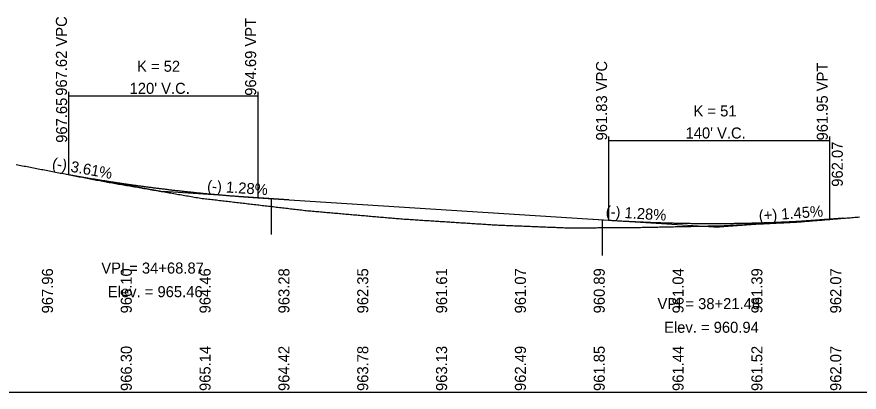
# Model space of a CAD drawing. Extents: x 1619269 to 1623088, y 1189107 to 1192385.
# Drawn here: x 1622052 to 1622587, y 1190357 to 1190595 of the extents above; entities that cross this region are included whole.
import ezdxf

# ---------------------------------------------------------------- set-up
doc = ezdxf.new("R2010")
doc.units = 0
for name, color, linetype in [('RD_DDB_GradeTX', 7, 'Continuous'), ('RD_DDB_Profile_EX', 7, 'Continuous'), ('RD_DDB_Profile_Lbl', 7, 'Continuous'), ('RD_DDB_Profile_PR', 7, 'Continuous'), ('RD_DDB_StripGrade', 7, 'Continuous'), ('RD_DDB_VCLbl', 7, 'Continuous'), ('RD_GPK_Profile_Cell', 7, 'Continuous'), ('RD_Sketch1', 7, 'Continuous')]:
    doc.layers.add(name, color=color, linetype=linetype)

msp = doc.modelspace()

# ---------------------------------------------------------------- linework, layer by layer
at = {"layer": 'RD_DDB_GradeTX'}
for p, q in [((1622084.17, 1190494.88), (1622145.04, 1190483.9)), ((1622224.88, 1190478.79), (1622145.04, 1190483.9)), ((1622417.82, 1190466.42), (1622497.65, 1190461.3)), ((1622576.17, 1190466.98), (1622497.65, 1190461.3))]:
    msp.add_line(p, q, dxfattribs=at)
at = {"layer": 'RD_DDB_Profile_EX'}
for points in [[(1622051.84, 1190501.04), (1622052.84, 1190500.86), (1622053.84, 1190500.68), (1622054.84, 1190500.5), (1622055.84, 1190500.33), (1622056.84, 1190500.15), (1622057.84, 1190499.97), (1622058.84, 1190499.78), (1622059.84, 1190499.58), (1622060.84, 1190499.39), (1622061.84, 1190499.2), (1622062.84, 1190499), (1622063.84, 1190498.81), (1622064.84, 1190498.62), (1622065.84, 1190498.42), (1622066.84, 1190498.23), (1622067.84, 1190498.04), (1622068.84, 1190497.84), (1622069.84, 1190497.65), (1622070.84, 1190497.46), (1622071.84, 1190497.26), (1622072.84, 1190497.07), (1622073.84, 1190496.88), (1622074.84, 1190496.68), (1622075.84, 1190496.49), (1622076.84, 1190496.3), (1622077.84, 1190496.1), (1622078.84, 1190495.91), (1622079.84, 1190495.71), (1622080.84, 1190495.52), (1622081.84, 1190495.33), (1622082.84, 1190495.13), (1622083.84, 1190494.94), (1622084.84, 1190494.75), (1622085.84, 1190494.55), (1622086.84, 1190494.36), (1622087.84, 1190494.17), (1622088.84, 1190493.97), (1622089.84, 1190493.78), (1622090.84, 1190493.59), (1622091.84, 1190493.39), (1622092.84, 1190493.2), (1622093.84, 1190493.01), (1622094.84, 1190492.81), (1622095.84, 1190492.62), (1622096.84, 1190492.43), (1622097.84, 1190492.23), (1622098.84, 1190492.04), (1622099.84, 1190491.85), (1622100.84, 1190491.65), (1622101.84, 1190491.46), (1622102.84, 1190491.27), (1622103.84, 1190491.07), (1622104.84, 1190490.88), (1622105.84, 1190490.68), (1622106.84, 1190490.49), (1622107.84, 1190490.3), (1622108.84, 1190490.11), (1622109.84, 1190489.95), (1622110.84, 1190489.77), (1622111.84, 1190489.6), (1622112.84, 1190489.43), (1622113.84, 1190489.26), (1622114.84, 1190489.08), (1622115.84, 1190488.91), (1622116.84, 1190488.74), (1622117.84, 1190488.56), (1622118.84, 1190488.39), (1622119.84, 1190488.22), (1622120.84, 1190488.05), (1622121.84, 1190487.87), (1622122.84, 1190487.7), (1622123.84, 1190487.53), (1622124.84, 1190487.35)], [(1622124.84, 1190487.35), (1622125.84, 1190487.18), (1622126.84, 1190487.01), (1622127.84, 1190486.84), (1622128.84, 1190486.66), (1622129.84, 1190486.49), (1622130.84, 1190486.32), (1622131.84, 1190486.14), (1622132.84, 1190485.97), (1622133.84, 1190485.8), (1622134.84, 1190485.63), (1622135.84, 1190485.45), (1622136.84, 1190485.28), (1622137.84, 1190485.11), (1622138.84, 1190484.93), (1622139.84, 1190484.76), (1622140.84, 1190484.59), (1622141.84, 1190484.42), (1622142.84, 1190484.24), (1622143.84, 1190484.07), (1622144.84, 1190483.9), (1622145.84, 1190483.72), (1622146.84, 1190483.55), (1622147.84, 1190483.38), (1622148.84, 1190483.21), (1622149.84, 1190483.03), (1622150.84, 1190482.86), (1622151.84, 1190482.69), (1622152.84, 1190482.51), (1622153.84, 1190482.34), (1622154.84, 1190482.17), (1622155.84, 1190482), (1622156.84, 1190481.82), (1622157.84, 1190481.65), (1622158.84, 1190481.48), (1622159.84, 1190481.3), (1622160.84, 1190481.13), (1622161.84, 1190480.96), (1622162.84, 1190480.79), (1622163.84, 1190480.61), (1622164.84, 1190480.44), (1622165.84, 1190480.27), (1622166.84, 1190480.09), (1622167.84, 1190479.92), (1622168.84, 1190479.77), (1622169.84, 1190479.64), (1622170.84, 1190479.53), (1622171.84, 1190479.41), (1622172.84, 1190479.29), (1622173.84, 1190479.18), (1622174.84, 1190479.06), (1622175.84, 1190478.94), (1622176.84, 1190478.82), (1622177.84, 1190478.71), (1622178.84, 1190478.59), (1622179.84, 1190478.47), (1622180.84, 1190478.36), (1622181.84, 1190478.24), (1622182.84, 1190478.12), (1622183.84, 1190478), (1622184.84, 1190477.89), (1622185.84, 1190477.77), (1622186.84, 1190477.65), (1622187.84, 1190477.53), (1622188.84, 1190477.42), (1622189.84, 1190477.3), (1622190.84, 1190477.18), (1622191.84, 1190477.07), (1622192.84, 1190476.95), (1622193.84, 1190476.83), (1622194.84, 1190476.71), (1622195.84, 1190476.6), (1622196.84, 1190476.48), (1622197.84, 1190476.36), (1622198.84, 1190476.24), (1622199.84, 1190476.13), (1622200.84, 1190476.01), (1622201.84, 1190475.89), (1622202.84, 1190475.78), (1622203.84, 1190475.66), (1622204.84, 1190475.54), (1622205.84, 1190475.42), (1622206.84, 1190475.31), (1622207.84, 1190475.19), (1622208.84, 1190475.07), (1622209.84, 1190474.96), (1622210.84, 1190474.84), (1622211.84, 1190474.72), (1622212.84, 1190474.6), (1622213.84, 1190474.49), (1622214.84, 1190474.37), (1622215.84, 1190474.25), (1622216.84, 1190474.13), (1622217.84, 1190474.02), (1622218.84, 1190473.9), (1622219.84, 1190473.78), (1622220.84, 1190473.67), (1622221.84, 1190473.55), (1622222.84, 1190473.43), (1622223.84, 1190473.31), (1622224.84, 1190473.2)], [(1622224.84, 1190473.2), (1622225.84, 1190473.08), (1622226.84, 1190472.96), (1622227.84, 1190472.84), (1622228.84, 1190472.73), (1622229.84, 1190472.61), (1622230.84, 1190472.49), (1622231.84, 1190472.38), (1622232.84, 1190472.26), (1622233.84, 1190472.14), (1622234.84, 1190472.02), (1622235.84, 1190471.91), (1622236.84, 1190471.8), (1622237.84, 1190471.71), (1622238.84, 1190471.62), (1622239.84, 1190471.54), (1622240.84, 1190471.45), (1622241.84, 1190471.36), (1622242.84, 1190471.27), (1622243.84, 1190471.19), (1622244.84, 1190471.1), (1622245.84, 1190471.01), (1622246.84, 1190470.93), (1622247.84, 1190470.84), (1622248.84, 1190470.75), (1622249.84, 1190470.66), (1622250.84, 1190470.58), (1622251.84, 1190470.49), (1622252.84, 1190470.4), (1622253.84, 1190470.31), (1622254.84, 1190470.23), (1622255.84, 1190470.14), (1622256.84, 1190470.05), (1622257.84, 1190469.97), (1622258.84, 1190469.88), (1622259.84, 1190469.79), (1622260.84, 1190469.7), (1622261.84, 1190469.62), (1622262.84, 1190469.53), (1622263.84, 1190469.44), (1622264.84, 1190469.36), (1622265.84, 1190469.27), (1622266.84, 1190469.18), (1622267.84, 1190469.09), (1622268.84, 1190469.01), (1622269.84, 1190468.92), (1622270.84, 1190468.83), (1622271.84, 1190468.75), (1622272.84, 1190468.66), (1622273.84, 1190468.57), (1622274.84, 1190468.48), (1622275.84, 1190468.4), (1622276.84, 1190468.31), (1622277.84, 1190468.22), (1622278.84, 1190468.13), (1622279.84, 1190468.05), (1622280.84, 1190467.96), (1622281.84, 1190467.87), (1622282.84, 1190467.79), (1622283.84, 1190467.7), (1622284.84, 1190467.61), (1622285.84, 1190467.52), (1622286.84, 1190467.44), (1622287.84, 1190467.35), (1622288.84, 1190467.26), (1622289.84, 1190467.18), (1622290.84, 1190467.09), (1622291.84, 1190467), (1622292.84, 1190466.91), (1622293.84, 1190466.83), (1622294.84, 1190466.74), (1622295.84, 1190466.65), (1622296.84, 1190466.57), (1622297.84, 1190466.51), (1622298.84, 1190466.44), (1622299.84, 1190466.38), (1622300.84, 1190466.32), (1622301.84, 1190466.25), (1622302.84, 1190466.19), (1622303.84, 1190466.12), (1622304.84, 1190466.06), (1622305.84, 1190466), (1622306.84, 1190465.93), (1622307.84, 1190465.87), (1622308.84, 1190465.8), (1622309.84, 1190465.74), (1622310.84, 1190465.68), (1622311.84, 1190465.61), (1622312.84, 1190465.55), (1622313.84, 1190465.48), (1622314.84, 1190465.42), (1622315.84, 1190465.35), (1622316.84, 1190465.29), (1622317.84, 1190465.23), (1622318.84, 1190465.16), (1622319.84, 1190465.1), (1622320.84, 1190465.03), (1622321.84, 1190464.97), (1622322.84, 1190464.91), (1622323.84, 1190464.84), (1622324.84, 1190464.78)], [(1622324.84, 1190464.78), (1622325.84, 1190464.71), (1622326.84, 1190464.65), (1622327.84, 1190464.59), (1622328.84, 1190464.52), (1622329.84, 1190464.46), (1622330.84, 1190464.39), (1622331.84, 1190464.33), (1622332.84, 1190464.27), (1622333.84, 1190464.2), (1622334.84, 1190464.14), (1622335.84, 1190464.07), (1622336.84, 1190464.01), (1622337.84, 1190463.95), (1622338.84, 1190463.88), (1622339.84, 1190463.82), (1622340.84, 1190463.75), (1622341.84, 1190463.69), (1622342.84, 1190463.62), (1622343.84, 1190463.56), (1622344.84, 1190463.5), (1622345.84, 1190463.43), (1622346.84, 1190463.37), (1622347.84, 1190463.3), (1622348.84, 1190463.24), (1622349.84, 1190463.18), (1622350.84, 1190463.11), (1622351.84, 1190463.05), (1622352.84, 1190462.98), (1622353.84, 1190462.92), (1622354.84, 1190462.86), (1622355.84, 1190462.79), (1622356.84, 1190462.74), (1622357.84, 1190462.69), (1622358.84, 1190462.65), (1622359.84, 1190462.61), (1622360.84, 1190462.57), (1622361.84, 1190462.53), (1622362.84, 1190462.49), (1622363.84, 1190462.45), (1622364.84, 1190462.41), (1622365.84, 1190462.37), (1622366.84, 1190462.33), (1622367.84, 1190462.29), (1622368.84, 1190462.25), (1622369.84, 1190462.21), (1622370.84, 1190462.17), (1622371.84, 1190462.13), (1622372.84, 1190462.09), (1622373.84, 1190462.05), (1622374.84, 1190462.01), (1622375.84, 1190461.97), (1622376.84, 1190461.93), (1622377.84, 1190461.89), (1622378.84, 1190461.85), (1622379.84, 1190461.81), (1622380.84, 1190461.77), (1622381.84, 1190461.73), (1622382.84, 1190461.69), (1622383.84, 1190461.65), (1622384.84, 1190461.61), (1622385.84, 1190461.57), (1622386.84, 1190461.52), (1622387.84, 1190461.48), (1622388.84, 1190461.44), (1622389.84, 1190461.4), (1622390.84, 1190461.36), (1622391.84, 1190461.32), (1622392.84, 1190461.28), (1622393.84, 1190461.24), (1622394.84, 1190461.2), (1622395.84, 1190461.16), (1622396.84, 1190461.11), (1622397.84, 1190461.07), (1622398.84, 1190461.03), (1622399.84, 1190460.99), (1622400.84, 1190460.95), (1622401.84, 1190460.93), (1622402.84, 1190460.94), (1622403.84, 1190460.94), (1622404.84, 1190460.95), (1622405.84, 1190460.95), (1622406.84, 1190460.96), (1622407.84, 1190460.96), (1622408.84, 1190460.97), (1622409.84, 1190460.97), (1622410.84, 1190460.98), (1622411.84, 1190460.98), (1622412.84, 1190460.99), (1622413.84, 1190460.99), (1622414.84, 1190461), (1622415.84, 1190461), (1622416.84, 1190461.01), (1622417.84, 1190461.01), (1622418.84, 1190461.02), (1622419.84, 1190461.02), (1622420.84, 1190461.03), (1622421.84, 1190461.03), (1622422.84, 1190461.04), (1622423.84, 1190461.04), (1622424.84, 1190461.05)], [(1622524.84, 1190463.5), (1622525.84, 1190463.55), (1622526.84, 1190463.6), (1622527.84, 1190463.65), (1622528.84, 1190463.7), (1622529.84, 1190463.75), (1622530.84, 1190463.8), (1622531.84, 1190463.85), (1622532.84, 1190463.9), (1622533.84, 1190463.95), (1622534.84, 1190464), (1622535.84, 1190464.05), (1622536.84, 1190464.1), (1622537.84, 1190464.14), (1622538.84, 1190464.19), (1622539.84, 1190464.24), (1622540.84, 1190464.29), (1622541.84, 1190464.34), (1622542.84, 1190464.39), (1622543.84, 1190464.44), (1622544.84, 1190464.49), (1622545.84, 1190464.53), (1622546.84, 1190464.58), (1622547.84, 1190464.65), (1622548.84, 1190464.74), (1622549.84, 1190464.82), (1622550.84, 1190464.9), (1622551.84, 1190464.98), (1622552.84, 1190465.06), (1622553.84, 1190465.15), (1622554.84, 1190465.23), (1622555.84, 1190465.31), (1622556.84, 1190465.39), (1622557.84, 1190465.48), (1622558.84, 1190465.56), (1622559.84, 1190465.64), (1622560.84, 1190465.72), (1622561.84, 1190465.81), (1622562.84, 1190465.89), (1622563.84, 1190465.97), (1622564.84, 1190466.05), (1622565.84, 1190466.13), (1622566.84, 1190466.22), (1622567.84, 1190466.3), (1622568.84, 1190466.38), (1622569.84, 1190466.46), (1622570.84, 1190466.55), (1622571.84, 1190466.63), (1622572.84, 1190466.71), (1622573.84, 1190466.79), (1622574.84, 1190466.87), (1622575.84, 1190466.96), (1622576.84, 1190467.04), (1622577.84, 1190467.12), (1622578.84, 1190467.2), (1622579.84, 1190467.29), (1622580.84, 1190467.37), (1622581.84, 1190467.45), (1622582.84, 1190467.53), (1622583.84, 1190467.62), (1622584.84, 1190467.7), (1622585.84, 1190467.78), (1622586.84, 1190467.86)], [(1622424.84, 1190461.05), (1622425.84, 1190461.05), (1622426.84, 1190461.06), (1622427.84, 1190461.06), (1622428.84, 1190461.07), (1622429.84, 1190461.07), (1622430.84, 1190461.08), (1622431.84, 1190461.08), (1622432.84, 1190461.09), (1622433.84, 1190461.09), (1622434.84, 1190461.1), (1622435.84, 1190461.1), (1622436.84, 1190461.11), (1622437.84, 1190461.11), (1622438.84, 1190461.12), (1622439.84, 1190461.12), (1622440.84, 1190461.13), (1622441.84, 1190461.13), (1622442.84, 1190461.14), (1622443.84, 1190461.15), (1622444.84, 1190461.17), (1622445.84, 1190461.19), (1622446.84, 1190461.21), (1622447.84, 1190461.23), (1622448.84, 1190461.25), (1622449.84, 1190461.27), (1622450.84, 1190461.29), (1622451.84, 1190461.31), (1622452.84, 1190461.33), (1622453.84, 1190461.35), (1622454.84, 1190461.37), (1622455.84, 1190461.39), (1622456.84, 1190461.41), (1622457.84, 1190461.43), (1622458.84, 1190461.45), (1622459.84, 1190461.47), (1622460.84, 1190461.49), (1622461.84, 1190461.51), (1622462.84, 1190461.53), (1622463.84, 1190461.55), (1622464.84, 1190461.57), (1622465.84, 1190461.59), (1622466.84, 1190461.61), (1622467.84, 1190461.63), (1622468.84, 1190461.65), (1622469.84, 1190461.67), (1622470.84, 1190461.69), (1622471.84, 1190461.71), (1622472.84, 1190461.73), (1622473.84, 1190461.75), (1622474.84, 1190461.77), (1622475.84, 1190461.79), (1622476.84, 1190461.81), (1622477.84, 1190461.83), (1622478.84, 1190461.85), (1622479.84, 1190461.87), (1622480.84, 1190461.89), (1622481.84, 1190461.91), (1622482.84, 1190461.93), (1622483.84, 1190461.95), (1622484.84, 1190461.97), (1622485.84, 1190461.99), (1622486.84, 1190462.01), (1622487.84, 1190462.03), (1622488.84, 1190462.05), (1622489.84, 1190462.07), (1622490.84, 1190462.09), (1622491.84, 1190462.11), (1622492.84, 1190462.13), (1622493.84, 1190462.15), (1622494.84, 1190462.17), (1622495.84, 1190462.19), (1622496.84, 1190462.21), (1622497.84, 1190462.23), (1622498.84, 1190462.25), (1622499.84, 1190462.29), (1622500.84, 1190462.32), (1622501.84, 1190462.37), (1622502.84, 1190462.42), (1622503.84, 1190462.47), (1622504.84, 1190462.52), (1622505.84, 1190462.57), (1622506.84, 1190462.62), (1622507.84, 1190462.67), (1622508.84, 1190462.72), (1622509.84, 1190462.77), (1622510.84, 1190462.82), (1622511.84, 1190462.86), (1622512.84, 1190462.91), (1622513.84, 1190462.96), (1622514.84, 1190463.01), (1622515.84, 1190463.06), (1622516.84, 1190463.11), (1622517.84, 1190463.16), (1622518.84, 1190463.21), (1622519.84, 1190463.26), (1622520.84, 1190463.31), (1622521.84, 1190463.36), (1622522.84, 1190463.41), (1622523.84, 1190463.46), (1622524.84, 1190463.5)]]:
    msp.add_lwpolyline(points, dxfattribs=at)
at = {"layer": 'RD_DDB_Profile_PR'}
for p, q in [((1622084.17, 1190494.88), (1622085.04, 1190494.72)), ((1622205.04, 1190480.06), (1622427.65, 1190465.79)), ((1622567.65, 1190466.37), (1622576.17, 1190466.98))]:
    msp.add_line(p, q, dxfattribs=at)
for points in [[(1622085.04, 1190494.72), (1622087.44, 1190494.29), (1622089.84, 1190493.87), (1622092.24, 1190493.45), (1622094.64, 1190493.03), (1622097.04, 1190492.63), (1622099.44, 1190492.22), (1622101.84, 1190491.83), (1622104.24, 1190491.44), (1622106.64, 1190491.05), (1622109.04, 1190490.67), (1622111.44, 1190490.3), (1622113.84, 1190489.93), (1622116.24, 1190489.57), (1622118.64, 1190489.21), (1622121.04, 1190488.86), (1622123.44, 1190488.51), (1622125.84, 1190488.17), (1622128.24, 1190487.84), (1622130.64, 1190487.51), (1622133.04, 1190487.18), (1622135.44, 1190486.86), (1622137.84, 1190486.55), (1622140.24, 1190486.24), (1622142.64, 1190485.94), (1622145.04, 1190485.65), (1622147.44, 1190485.36), (1622149.84, 1190485.07), (1622152.24, 1190484.79), (1622154.64, 1190484.52), (1622157.04, 1190484.25), (1622159.44, 1190483.99), (1622161.84, 1190483.73), (1622164.24, 1190483.48), (1622166.64, 1190483.23), (1622169.04, 1190482.99), (1622171.44, 1190482.76), (1622173.84, 1190482.53), (1622176.24, 1190482.31), (1622178.64, 1190482.09), (1622181.04, 1190481.88), (1622183.44, 1190481.67), (1622185.84, 1190481.47), (1622188.24, 1190481.27), (1622190.64, 1190481.08), (1622193.04, 1190480.9), (1622195.44, 1190480.72), (1622197.84, 1190480.55), (1622200.24, 1190480.38), (1622202.64, 1190480.22), (1622205.04, 1190480.06)], [(1622427.65, 1190465.79), (1622430.45, 1190465.61), (1622433.25, 1190465.45), (1622436.05, 1190465.29), (1622438.85, 1190465.13), (1622441.65, 1190464.99), (1622444.45, 1190464.85), (1622447.25, 1190464.72), (1622450.05, 1190464.6), (1622452.85, 1190464.48), (1622455.65, 1190464.38), (1622458.45, 1190464.28), (1622461.25, 1190464.19), (1622464.05, 1190464.1), (1622466.85, 1190464.03), (1622469.65, 1190463.96), (1622472.45, 1190463.9), (1622475.25, 1190463.84), (1622478.05, 1190463.8), (1622480.85, 1190463.76), (1622483.65, 1190463.73), (1622486.45, 1190463.71), (1622489.25, 1190463.69), (1622492.05, 1190463.68), (1622494.85, 1190463.68), (1622497.65, 1190463.69), (1622500.45, 1190463.71), (1622503.25, 1190463.73), (1622506.05, 1190463.76), (1622508.85, 1190463.8), (1622511.65, 1190463.84), (1622514.45, 1190463.9), (1622517.25, 1190463.96), (1622520.05, 1190464.03), (1622522.85, 1190464.1), (1622525.65, 1190464.19), (1622528.45, 1190464.28), (1622531.25, 1190464.38), (1622534.05, 1190464.49), (1622536.85, 1190464.6), (1622539.65, 1190464.72), (1622542.45, 1190464.85), (1622545.25, 1190464.99), (1622548.05, 1190465.14), (1622550.85, 1190465.29), (1622553.65, 1190465.45), (1622556.45, 1190465.62), (1622559.25, 1190465.79), (1622562.05, 1190465.98), (1622564.85, 1190466.17), (1622567.65, 1190466.37)]]:
    msp.add_spline(points, degree=3, dxfattribs=at)
at = {"layer": 'RD_DDB_VCLbl'}
for p, q in [((1622085.04, 1190547.22), (1622085.04, 1190494.72)), ((1622085.04, 1190544.72), (1622205.04, 1190544.72)), ((1622205.04, 1190547.22), (1622205.04, 1190480.06)), ((1622427.65, 1190518.87), (1622427.65, 1190465.79)), ((1622567.65, 1190518.87), (1622567.65, 1190466.37)), ((1622427.65, 1190516.37), (1622567.65, 1190516.37))]:
    msp.add_line(p, q, dxfattribs=at)
at = {"layer": 'RD_GPK_Profile_Cell'}
msp.add_line((1621576.17, 1190356.62), (1623076.17, 1190356.62), dxfattribs=at)
at = {"layer": 'RD_Sketch1'}
for p, q in [((1622213.71, 1190456.62), (1622213.71, 1190479.5)), ((1622423.71, 1190443.37), (1622423.71, 1190466.04))]:
    msp.add_line(p, q, dxfattribs=at)

# ---------------------------------------------------------------- texts
at = {"layer": 'RD_DDB_GradeTX'}
for s, rotation, p in [('(-) 3.61%', 349.7814, (1622074.23, 1190498.7)), ('(-) 1.28%', 356.3325, (1622172.8, 1190484.13)), ('(-) 1.28%', 356.3325, (1622425.61, 1190467.92)), ('(+) 1.45%', 4.1382, (1622523.11, 1190465.15))]:
    msp.add_text(s, height=7, rotation=rotation, dxfattribs=at).set_placement(p)
at = {"layer": 'RD_DDB_Profile_Lbl'}
for s, p in [('967.65', (1622084.17, 1190514.88)), ('962.07', (1622576.17, 1190486.98))]:
    msp.add_text(s, height=7, rotation=90, dxfattribs=at).set_placement(p)
for s, p in [('VPI = 34+68.87', (1622105.85, 1190431.9)), ('Elev. = 965.46', (1622109.99, 1190416.9)), ('VPI = 38+21.48', (1622458.63, 1190409.3)), ('Elev. = 960.94', (1622462.79, 1190394.3))]:
    msp.add_text(s, height=7, dxfattribs=at).set_placement(p)
at = {"layer": 'RD_DDB_StripGrade'}
for s, p in [('967.62 VPC', (1622084.04, 1190544.72)), ('964.69 VPT', (1622204.04, 1190544.72)), ('961.83 VPC', (1622426.65, 1190516.37)), ('961.95 VPT', (1622566.65, 1190516.37)), ('967.96', (1622075.17, 1190406.62)), ('966.10', (1622125.17, 1190406.62)), ('964.46', (1622175.17, 1190406.62)), ('963.28', (1622225.17, 1190406.62)), ('962.35', (1622275.17, 1190406.62)), ('961.61', (1622325.17, 1190406.62)), ('961.07', (1622375.17, 1190406.62)), ('960.89', (1622425.17, 1190406.62)), ('961.04', (1622475.17, 1190406.62)), ('961.39', (1622525.17, 1190406.62)), ('962.07', (1622575.17, 1190406.62)), ('966.30', (1622125.17, 1190357.37)), ('965.14', (1622175.17, 1190357.37)), ('964.42', (1622225.17, 1190357.37)), ('963.78', (1622275.17, 1190357.37)), ('963.13', (1622325.17, 1190357.37)), ('962.49', (1622375.17, 1190357.37)), ('961.85', (1622425.17, 1190357.37)), ('961.44', (1622475.17, 1190357.37)), ('961.52', (1622525.17, 1190357.37)), ('962.07', (1622575.17, 1190357.37))]:
    msp.add_text(s, height=7, rotation=90, dxfattribs=at).set_placement(p)
at = {"layer": 'RD_DDB_VCLbl'}
for s, p in [('K = 52', (1622128.5, 1190559.97)), ("120' V.C.", (1622123.79, 1190545.97)), ('K = 51', (1622481.46, 1190531.62)), ("140' V.C.", (1622476.4, 1190517.62))]:
    msp.add_text(s, height=7, dxfattribs=at).set_placement(p)

doc.saveas('drawing.dxf')
